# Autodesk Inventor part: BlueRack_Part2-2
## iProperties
Shininess: 64.0
Length Units: 11272
Angle Units: 11279
Time Units: 11290
Mass Units: 11286
Length Display Precision: 3
Angle Display Precision: 2
Compacted: True
Part Number: BlueRack_Part2-2
Document SubType Name: Modeling
Created: 2004-12
Designer: John Blackburn
Material: Steel, Mild
Manufacturer: Standard
Standards Organization: Custom
Density: 0.0
Volumn: 0.0
Area: 0.0
PropertySet Name: Model Information
Control State: 0
Master: False
Checked Out: False
Author: John Blackburn
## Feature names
1. Extrusion1
2. Hole3
3. Rectangular Pattern3
4. Hole4
5. Rectangular Pattern4
6. Hole5
7. Rectangular Pattern5
